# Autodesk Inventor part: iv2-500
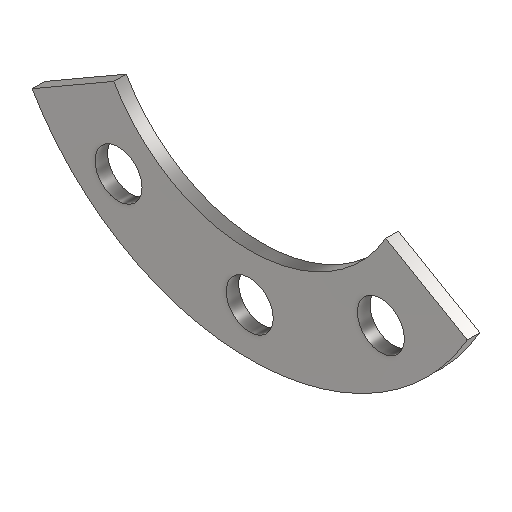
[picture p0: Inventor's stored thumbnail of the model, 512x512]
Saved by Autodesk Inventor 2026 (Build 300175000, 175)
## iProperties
Created: 2022-01
Part Number: iv2-500
Material: Steel, Mild
Document SubType Name: Modeling
Designer: Lars Bertram Pedersen
Density: 7.85 g/cm^3
Appearance: Semi-Polished
Author: Lars Bertram Pedersen
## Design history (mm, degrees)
sketch "Sketch1"
  geometry: L1 (-21.651, -12.5)-(-34.641, -20); L2 (21.651, -12.5)-(34.641, -20); L3 (-21.651, -12.5)-(0, 0); L4 (0, 0)-(21.651, -12.5); L5 (0, 0)-(-20.891, -24.896); L6 (0, 0)-(20.891, -24.896); C1 r 3.75 at (-20.891, -24.896); C2 r 3.75 at (0, -32.5); C3 r 3.75 at (20.891, -24.896); A1 r 25 centre (0, 0) between (-21.651, -12.5) and (21.651, -12.5); A2 r 40 centre (0, 0) between (-34.641, -20) and (34.641, -20); A3 r 32.5 centre (0, 0) between (-28.146, -16.25) and (28.146, -16.25); 1 further point
  constraints: 12 end point, 10 point on circle, 6 centre point, 3 coincident, 2 collinear, 2 equal radius, 2 horizontal alignment, 1 midpoint, 1 vertical alignment
  dimensions: "d0" = 25 radius of A1; "d2" = 120 deg angle of L2 L1; "d3" = 20 deg angle of L5 L3; "d4" = 7.5 diameter of C1; "d5" = 15 distance of L1.start L1.end
extrude "Extrusion1" new body sketch "Sketch1" distance "d6" = 2; taper "d7" = 0 deg
body "Solid1"
